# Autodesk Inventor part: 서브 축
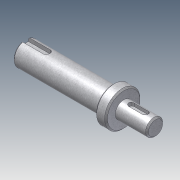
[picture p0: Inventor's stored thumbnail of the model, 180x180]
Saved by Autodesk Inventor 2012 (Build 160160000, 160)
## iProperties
Company: 한국ATC센터
Created: 2014-10
Part Number: 서브 축
Document SubType Name: Modeling
Designer: KYOUNG IL JANG
Density: 1 g/cm^3
Mass: 19.9624 g
Surface Area: 57.7178 cm^2
Volume: 19.9624 cm^3
Material: 기본값
Author: KYOUNG IL JANG
Revision Number: 1
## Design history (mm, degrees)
sketch "스케치1"
  geometry: L1 (-16.331, 0)-(-108.831, 0); L2 (-16.331, 0)-(-16.331, -6); L3 (-16.331, -6)-(-38.831, -6); L4 (-38.831, -12.5)-(-46.5, -12.5); L5 (-46.5, -8.5)-(-108.831, -8.5); L6 (-108.831, -8.5)-(-108.831, 0); L7 (-46.5, -8.5)-(-46.5, -12.5); L8 (-38.831, -6)-(-38.831, -12.5); L9 (-46.5, 12.249)-(-46.5, -12.249) reference; L10 (-38.831, -17)-(-38.831, 17) reference; 2 further points
  constraints: 17 end point, 4 perpendicular, 2 collinear, 2 parallel, 1 horizontal, 1 midpoint, 1 point on line
  dimensions: "d1" = 12 diameter of L3 L1; "d2" = 25 diameter of L4 L1; "d3" = 17 diameter of L5 L1; "d4" = 62.33128 distance of L5.start L5.end (derived); "d18" = 22.5 distance of L2.end L3.end; "d20" = 70 distance between parallel lines of L6 L8
revolve "회전1" sketch "스케치1" stored, may be unused: angle "d5" = 90 deg
chamfer "모따기1" distance "d6" = 1; stored, may be unused: second distance "d7" = 2, angle "d8" = 45 deg
node "작업 평면1"
sketch "스케치2"
  geometry: L1 (11.25, 5)-(11.25, -5) reference; L2 (-5.75, -2)-(4.25, -2); L3 (4.25, 2)-(-5.75, 2); A1 r 2 centre (4.25, 0) between (4.25, -2) and (4.25, 2); A2 r 2 centre (-5.75, 0) between (-5.75, 2) and (-5.75, -2); 2 further points
  constraints: 4 end point, 4 point on circle, 4 tangent, 2 centre point, 1 horizontal alignment, 1 midpoint, 1 parallel, 1 perpendicular
  dimensions: "d9" = 4 distance between parallel lines of L2 L3; "d10" = 14 dimension on A1 A2; "d11" = 5 distance edge to line of A1 L1
extrude "돌출1" cut sketch "스케치2" distance "d12" = 2.5; taper "d13" = 0 deg
node "작업 평면2"
sketch "스케치3"
  geometry: L1 (-31.166, -7.5)-(-31.166, 7.5) reference; L2 (-31.166, 2.5)-(-15.666, 2.5); L3 (-15.666, -2.5)-(-31.166, -2.5); A1 r 2.5 centre (-15.666, 0) between (-15.666, -2.5) and (-15.666, 2.5); 2 further points
  constraints: 4 end point, 2 perpendicular, 2 point on circle, 2 point on line, 2 tangent, 1 centre point, 1 horizontal alignment, 1 midpoint
  dimensions: "d14" = 5 distance between parallel lines of L3 L2; "d15" = 18 dimension on A1 L1
extrude "돌출2" cut sketch "스케치3" distance "d16" = 3; taper "d17" = 0 deg
node "솔리드1"
node "참조4"
node "참조5"
